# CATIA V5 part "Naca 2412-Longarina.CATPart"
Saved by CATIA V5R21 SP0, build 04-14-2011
Part number: Naca 2412
Bounding box of the stored display mesh (mm): x 0 to 200, y -8.48 to 15.76, z 0 to 82.2
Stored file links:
  C:\Users\andre\OneDrive\Documentos\UNB-FGA\3_Semestre\Sistemas Aeroespaciais\Naca 2412-Longarina.CATPart
  C:\Users\andre\AppData\Local\Temp\Rar$DIa18808.12376\NACA 2412 3D Aerofoil.CATPart
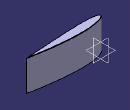
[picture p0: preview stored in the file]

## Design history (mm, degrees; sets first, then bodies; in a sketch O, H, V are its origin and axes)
Body1 (main body)
  Sketch1 on xy-plane, origin (0, 0, 0), H (1, 0, 0), V (0, 1, 0)
    unspec C1
    unspec C2
    point P3 (26.5548, 0)
    circle A1 centre (20, 2) radius 5
    point P4 (20, 2)
    point P5 (24.5826, 0)
    line L1 (30, 11) -> (36, 11)
    line L2 (36, 11) -> (36, -6)
    line L3 (36, -6) -> (30, -6)
    line L4 (30, -6) -> (30, 11)
    circle A2 centre (50, 3) radius 7.5
    point P10 (50, 3)
    circle A3 centre (75, 4) radius 7.5
    point P11 (75, 4)
    circle A4 centre (100, 4) radius 7.5
    point P12 (100, 4)
    circle A5 centre (125, 3) radius 5
    point P13 (125, 3)
    line L5 (140, 8) -> (144, 8)
    line L6 (144, 8) -> (144, -2)
    line L7 (144, -2) -> (140, -2)
    line L8 (140, -2) -> (140, 8)
    radius A1 = 5
    distance H P4 = 2
    distance V P4 = 20
    distance L4 L2 = 6
    distance L1 L3 = 17
    distance L3 H = 6
    distance L4 V = 30
    radius A2 = 7.5
    distance P10 H = 3
    distance P10 V = 50
    radius A3 = 7.5
    distance P11 H = 4
    distance P11 V = 75
    radius A4 = 7.5
    distance P12 H = 4
    distance P12 V = 100
    radius A5 = 5
    distance P13 H = 3
    distance P13 V = 125
    distance L5 L7 = 10
    distance L8 L6 = 4
    distance L8 V = 140
    distance L7 H = 2
    coincidence: A1 P5, P5 H
    horizontal: L1 H, L3 H, L5 H, L7 H
    vertical: L2 V, L4 V, L6 V, L8 V
  Pad1: profile Sketch1, direction (0, 0, 1), length 77.2
  Sketch2 on end face of Pad1, origin (0, 0, 77.2), H (1, 0, 0), V (0, 1, 0)
    unspec C1
    unspec C2
  Pad2: profile Sketch2, direction (0, 0, 1), length 5
  Fillet1: radius 1, on edge [face of Pad2 | end face of Pad2]; end face of Pad2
